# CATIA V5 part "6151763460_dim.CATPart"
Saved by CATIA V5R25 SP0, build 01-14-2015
Part number: 6151763460_dim
Source: made
Property "PROI_CREATED_ON": "12/17/2008 9:21:37 AM"
Property "BLANK_DRAWING": "--"
Property "DRAWN_BY": "FPA"
Property "FINISH": "--"
Property "HEAT_TREATMENT": "ASSIGN"
Property "MATERIAL": "ASSIGN"
Property "PROJECT": "--"
Property "PROTOTYPE_NO": "--"
Property "RELATED_DRAWING": "--"
Property "COMPLETE_MATERIAL": "ASSIGN-ASSIGN"
Property "DESCRIPTION": "XPBMC-6000-P"
Property "DRAWING_EXIST": "--"
Property "MANUFACTURER": "--"
Property "MANUFACTURER_2": "--"
Property "MANUFACTURER_REF": "--"
Property "TYPE_PART": "A"
Property "TODAY_DATE": "2024/11/08"
Property "PDMREV": "01.0"
Property "PDMRL": "Production"
Property "PROI_REVISION": "01"
Property "PROI_VERSION": "0"
Property "PROI_RELEASE": "Production"
Property "PTC_MODIFIED": false
Property "MFG_WP_MATERIAL": "ASSIGN"
Property "COMPANY_CODE": "---"
Property "DESCRIPTION_JP": "--"
Property "PQP_DOCUMENT": "--"
Property "SUPPLIER": "--"
Property "REFERENCE": "6151763440"
Property "PTC_WM_REVISION": "01"
Property "PTC_WM_ITERATION": "0"
Property "PTC_WM_VERSION": "01.0"
Property "PTC_WM_LIFECYCLE_STATE": "Production"
Property "PTC_WM_LIFECYCLE": "Design_Process"
Property "PTC_WM_LOCATION": "/Products/DRILLS TOOLS ASC/A1780 - XPB/9-01-Dimensional Drawings and 3D"
Property "PTC_WM_CREATED_BY": "Florian Pavageau (Grefpav) (Grefpav: CPD)"
Property "PTC_WM_CREATED_ON": "08-Nov-24 01:56:40 PM"
Property "PTC_WM_MODIFIED_BY": "Florian Pavageau (Grefpav) (Grefpav: CPD)"
Property "PTC_WM_MODIFIED_ON": "08-Nov-24 02:23:08 PM"
Property "PTC_WM_TEAM": "Default"
Property "PTC_ORGANIZATION_ID": "CPD"
Property "EXPORT_CONTROL": "NULL"
Property "PTC_WM_NAME": "6151763460_dim.prt"
Property "PTC_WM_NUMBER": "6151763460_DIM.PRT"
Property "PTC_COMMON_NAME": "6151763460_dim.prt"
Property "PTC_MASTER_MATERIAL": "ASSIGN"
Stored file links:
  d:\ptc\Echange\temp\6151763460_dim.CATPart

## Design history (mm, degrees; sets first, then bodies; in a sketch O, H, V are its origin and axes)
AxisSystem1 "CS0": origin (0, 0, 0), X (1, 0, 0), Y (0, 1, 0), Z (0, 0, 1)
Set1
  DatumSurface1 "Sheet.1"
  DatumSurface2 "Sheet.2"
  DatumSurface3 "Sheet.3"
  DatumSurface4 "Sheet.4"
  DatumSurface5 "Sheet.5"
  DatumSurface6 "Sheet.6"
  DatumSurface7 "Sheet.7"
  DatumSurface8 "Sheet.8"
  DatumSurface9 "Sheet.9"
  DatumSurface10 "Sheet.10"
  DatumSurface11 "Sheet.11"
  DatumSurface12 "Sheet.12"
  DatumSurface13 "Sheet.13"
  DatumSurface14 "Sheet.14"
  DatumSurface15 "Sheet.15"
  DatumSurface16 "Sheet.16"
  DatumSurface17 "Sheet.17"
  DatumSurface18 "Sheet.18"
  DatumSurface19 "Sheet.19"
  DatumSurface20 "Sheet.20"
  DatumSurface21 "Sheet.21"
  DatumSurface22 "Sheet.22"
  DatumSurface23 "Sheet.23"
  DatumSurface24 "Sheet.24"
  DatumSurface25 "Sheet.25"
  DatumSurface26 "Sheet.26"
  DatumSurface27 "Sheet.27"
  DatumSurface28 "Sheet.28"
  DatumSurface29 "Sheet.29"
  DatumSurface30 "Sheet.30"
  DatumSurface31 "Sheet.31"
  DatumSurface32 "Sheet.32"
  DatumSurface33 "Sheet.33"
  DatumSurface34 "Sheet.34"
  DatumSurface35 "Sheet.35"
  DatumSurface36 "Sheet.36"
  DatumSurface37 "Sheet.37"
  DatumSurface38 "Sheet.38"
  DatumSurface39 "Sheet.39"
  DatumSurface40 "Sheet.40"
  DatumSurface41 "Sheet.41"
  DatumSurface42 "Sheet.42"
  Plane1 "RIGHT": stored without definition
  Plane2 "TOP": stored without definition
  Plane3 "FRONT": stored without definition
Body1 "PartBody" (main body)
